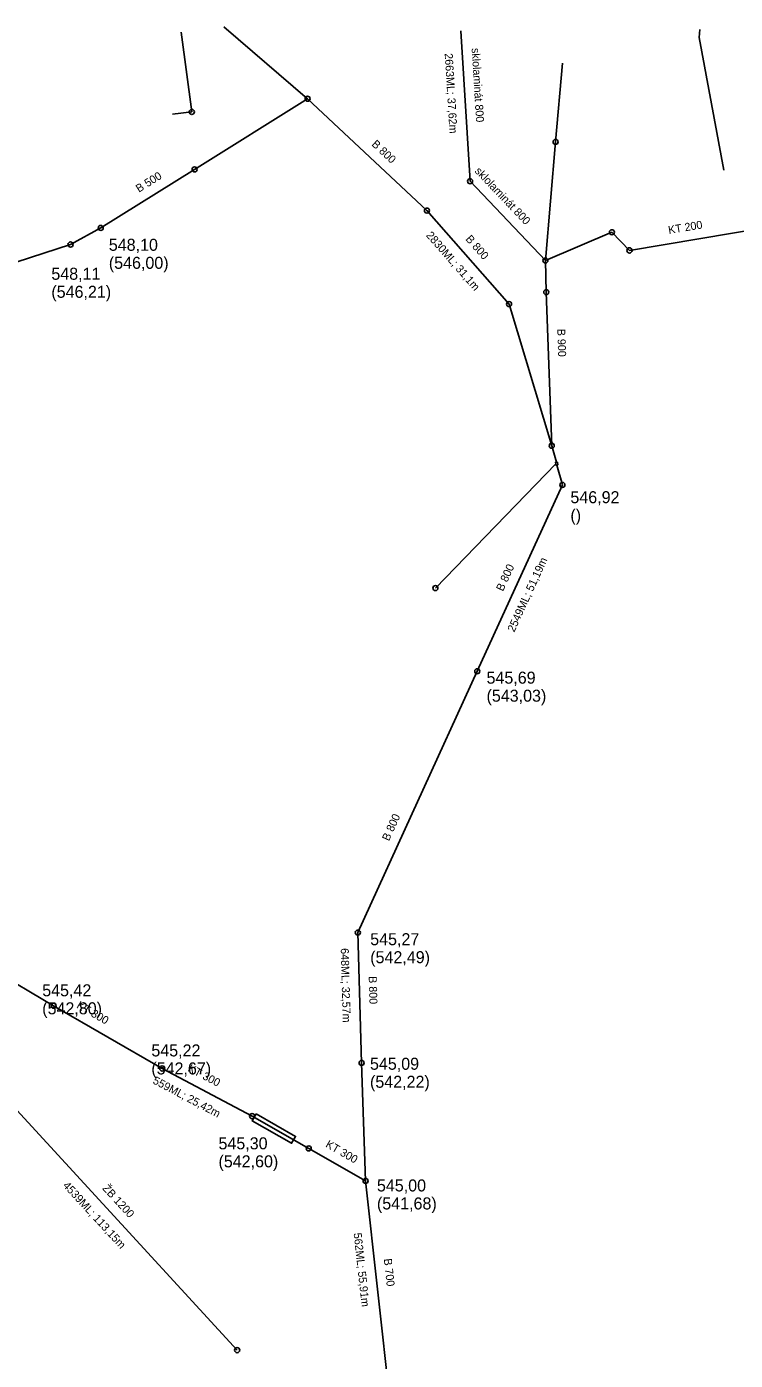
# Model space of a CAD drawing. Extents: x -867696 to -865033, y -1042522 to -1039817.
# Drawn here: x -865995.7 to -865818.6, y -1040292.2 to -1039959 of the extents above; entities that cross this region are included whole.
import ezdxf

# ---------------------------------------------------------------- set-up
doc = ezdxf.new("R2010")
doc.units = 0
for name, color, linetype in [('KN - jednotna', 7, 'Continuous'), ('KN - jina', 7, 'Continuous'), ('KN - ostatni', 7, 'Continuous'), ('KN - popis material', 7, 'Continuous'), ('KN - popis ostatni', 7, 'Continuous'), ('KN - popis usek delka', 7, 'Continuous'), ('KN - pripojka', 7, 'Continuous'), ('KN - sachta komora', 7, 'Continuous'), ('Level 1', 7, 'Continuous'), ('V - pripojka', 7, 'Continuous')]:
    doc.layers.add(name, color=color, linetype=linetype)

# ---------------------------------------------------------------- blocks, each defined once
blk = doc.blocks.new('100.M')
at = {"layer": 'Level 1'}
blk.add_circle((0, 0), 1.27, dxfattribs=at)

msp = doc.modelspace()

# ---------------------------------------------------------------- linework, layer by layer
at = {"layer": 'KN - jednotna'}
for points in [[(-865957.168, -1039960.377), (-865954.461, -1039980.298)], [(-865925.522, -1039976.986), (-865946.476, -1039958.986)], [(-865884.9, -1039997.6), (-865887.19, -1039960.05)], [(-865861.77, -1039968.111), (-865863.523, -1039987.773)], [(-865925.522, -1039976.986), (-865953.781, -1039994.631)], [(-865895.685, -1040004.926), (-865925.522, -1039976.986)], [(-865863.523, -1039987.773), (-865866.09, -1040017.4)], [(-865953.781, -1039994.631), (-865977.23, -1040009.272)], [(-865866.09, -1040017.4), (-865884.9, -1039997.6)], [(-865875.167, -1040028.292), (-865895.685, -1040004.926)], [(-865977.23, -1040009.272), (-865984.776, -1040013.42)], [(-865866.09, -1040017.4), (-865849.446, -1040010.35)], [(-865849.446, -1040010.35), (-865845.071, -1040014.883)], [(-865845.071, -1040014.883), (-865810.373, -1040009.065)], [(-865984.776, -1040013.42), (-866022.068, -1040025.442)], [(-865866.09, -1040017.4), (-865865.849, -1040025.313)], [(-865875.167, -1040028.292), (-865864.497, -1040063.667)], [(-865865.849, -1040025.313), (-865864.497, -1040063.667)], [(-865864.497, -1040063.667), (-865863.332, -1040067.819)], [(-865863.201, -1040068.513), (-865861.819, -1040073.468)], [(-865861.819, -1040073.468), (-865883.105, -1040120.024)], [(-865883.105, -1040120.024), (-865912.959, -1040185.318)], [(-865912.037, -1040217.87), (-865912.959, -1040185.318)], [(-866013.768, -1040188.928), (-865989.019, -1040203.588)], [(-865989.019, -1040203.588), (-865961.858, -1040219.258)], [(-865912.037, -1040217.87), (-865911.028, -1040247.358)], [(-865961.858, -1040219.258), (-865939.397, -1040231.168)], [(-865939.397, -1040231.168), (-865925.237, -1040239.237)], [(-865925.237, -1040239.237), (-865911.028, -1040247.358)], [(-865911.028, -1040247.358), (-865904.917, -1040302.93)]]:
    msp.add_lwpolyline(points, dxfattribs=at)
at = {"layer": 'KN - jina'}
for points in [[(-865863.497, -1040068.209), (-865893.588, -1040099.235)], [(-866019.733, -1040206.342), (-865943.134, -1040289.625)]]:
    msp.add_lwpolyline(points, dxfattribs=at)
at = {"layer": 'KN - ostatni'}
msp.add_lwpolyline([(-865938.364, -1040230.606), (-865928.516, -1040236.217), (-865929.507, -1040237.955), (-865939.354, -1040232.343), (-865938.364, -1040230.606)], dxfattribs=at)
at = {"layer": 'KN - pripojka'}
msp.add_lwpolyline([(-865954.461, -1039980.298), (-865959.32, -1039980.817)], dxfattribs=at)
at = {"layer": 'KN - sachta komora'}
msp.add_lwpolyline([(-865863.091, -1040067.781), (-865863.573, -1040067.857), (-865863.421, -1040068.56), (-865862.981, -1040068.467), (-865863.091, -1040067.781)], dxfattribs=at)
at = {"layer": 'V - pripojka'}
msp.add_lwpolyline([(-865827.504, -1039959.679), (-865827.678, -1039961.678), (-865821.509, -1039994.87)], dxfattribs=at)

# ---------------------------------------------------------------- block references
at = {"layer": 'KN - sachta komora'}
for p, xscale, yscale, rotation in [((-865925.522, -1039976.986), 0.5000000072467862, 0.5000000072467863, 139.00000089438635), ((-865954.461, -1039980.298), 0.49999999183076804, 0.49999999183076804, -81.99999961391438), ((-865863.523, -1039987.773), 0.500000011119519, 0.5000000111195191, 85.00000001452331), ((-865953.781, -1039994.631), 0.4999999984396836, 0.49999999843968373, 32.00000027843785), ((-865884.9, -1039997.6), 0.49999998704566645, 0.49999998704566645, 114.00000060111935), ((-865895.685, -1040004.926), 0.4999999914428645, 0.49999999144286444, 135), ((-865977.23, -1040009.272), 0.5000000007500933, 0.5000000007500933, -149.00000017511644), ((-865849.446, -1040010.35), 0.5030333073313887, 0.5030333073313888, -12.654735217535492), ((-865984.776, -1040013.42), 0.5099284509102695, 0.5099284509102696, -153.606016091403), ((-865845.071, -1040014.883), 0.516753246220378, 0.516753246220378, -23.041281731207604), ((-865866.09, -1040017.4), 0.5000000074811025, 0.5000000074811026, -90.99999994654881), ((-865865.849, -1040025.313), 0.500000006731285, 0.5000000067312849, -88.00000009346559), ((-865875.167, -1040028.292), 0.4999999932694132, 0.4999999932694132, 120.00000044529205), ((-865864.497, -1040063.667), 0.5036654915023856, 0.5036654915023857, 12.13890866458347), ((-865861.819, -1040073.468), 0.5000000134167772, 0.5000000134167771, -93.99999971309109), ((-865893.588, -1040099.235), 0.5000000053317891, 0.5000000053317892, -134.00000165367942), ((-865883.105, -1040120.024), 0.49999998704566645, 0.49999998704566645, -114.00000060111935), ((-865912.959, -1040185.318), 0.499999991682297, 0.4999999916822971, 78.9999997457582), ((-865989.019, -1040203.588), 0.4999999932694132, 0.4999999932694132, 149.99999955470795), ((-865961.858, -1040219.258), 0.5036281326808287, 0.5036281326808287, 151.23333487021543), ((-865912.037, -1040217.87), 0.500000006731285, 0.5000000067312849, 91.99999990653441), ((-865939.397, -1040231.168), 0.5036281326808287, 0.5036281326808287, 151.23333487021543), ((-865925.237, -1040239.237), 0.5018521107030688, 0.5018521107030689, 150.62079160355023), ((-865911.028, -1040247.358), 0.500000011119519, 0.5000000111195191, 94.99999998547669), ((-865943.134, -1040289.625), 0.50000000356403, 0.50000000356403, -46.99999943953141)]:
    msp.add_blockref('100.M', p, dxfattribs=dict(at, xscale=xscale, yscale=yscale, rotation=rotation))

# ---------------------------------------------------------------- texts
at = {"layer": 'KN - popis material'}
for s, height, rotation, p in [('sklolaminát 800', 1.99999, 273.49, (-865884.522, -1039964.377)), ('B 800', 2, 316.88, (-865909.674, -1039988.538)), ('sklolaminát 800', 1.99999, 313.53, (-865883.877, -1039995.192)), ('B 500', 2, 31.98, (-865967.689, -1040000.485)), ('KT 200', 2, 9.52, (-865835.214, -1040010.797)), ('B 800', 2, 311.29, (-865886.173, -1040012.122)), ('B 900', 2, 272.02, (-865863.123, -1040034.505)), ('B 800', 2, 65.43, (-865876.681, -1040100.202)), ('B 800', 2, 65.43, (-865905.203, -1040162.582)), ('B 800', 2, 271.62, (-865910.248, -1040196.23)), ('KT 300', 2, 330.02, (-865983.453, -1040204.029)), ('KT 300', 2, 332.07, (-865955.649, -1040219.834)), ('KT 300', 2, 330.25, (-865921.209, -1040238.775)), ('ŽB 1200', 2, 312.61, (-865976.953, -1040249.311)), ('B 700', 2, 276.28, (-865906.473, -1040266.834))]:
    msp.add_text(s, height=height, rotation=rotation, dxfattribs=at).set_placement(p)
at = {"layer": 'KN - popis ostatni'}
for s, p in [('548,10 ', (-865975.21, -1040014.982)), ('(546,00)', (-865975.21, -1040019.482)), ('548,11 ', (-865989.576, -1040022.22)), ('(546,21)', (-865989.576, -1040026.72)), ('546,92 ', (-865859.829, -1040078.038)), ('()', (-865859.829, -1040082.538)), ('545,69 ', (-865880.795, -1040123.124)), ('(543,03)', (-865880.795, -1040127.624)), ('545,27 ', (-865909.869, -1040188.458)), ('(542,49)', (-865909.869, -1040192.958)), ('545,42 ', (-865991.859, -1040201.228)), ('(542,80)', (-865991.859, -1040205.728)), ('545,22 ', (-865964.578, -1040216.248)), ('(542,67)', (-865964.578, -1040220.748)), ('545,09 ', (-865909.927, -1040219.58)), ('(542,22)', (-865909.927, -1040224.08)), ('545,30 ', (-865947.797, -1040239.458)), ('(542,60)', (-865947.797, -1040243.958)), ('545,00 ', (-865908.188, -1040249.978)), ('(541,68)', (-865908.188, -1040254.478))]:
    msp.add_text(s, height=3, dxfattribs=at).set_placement(p)
at = {"layer": 'KN - popis usek delka'}
for s, rotation, p in [('2663ML; 37,62m', 273.49, (-865891.255, -1039965.689)), ('2830ML; 31,1m', 311.29, (-865896.034, -1040011.199)), ('2549ML; 51,19m', 65.43, (-865873.865, -1040110.396)), ('648ML; 32,57m', 271.62, (-865917.25, -1040189.227)), ('559ML; 25,42m', 332.07, (-865964.4, -1040222.891)), ('4539ML; 113,15m', 312.61, (-865986.832, -1040248.615)), ('562ML; 55,91m', 276.28, (-865914.019, -1040260.421))]:
    msp.add_text(s, height=1.99999, rotation=rotation, dxfattribs=at).set_placement(p)

doc.saveas('drawing.dxf')
